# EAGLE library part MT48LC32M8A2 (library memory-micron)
256Mb: x16 SDRAM MT48LC32M8A2 - 8 Meg x 8 x 4 banks Source: http://download.micron.com/pdf/datasheets/dram/sdram/256MSDRAM.pdf
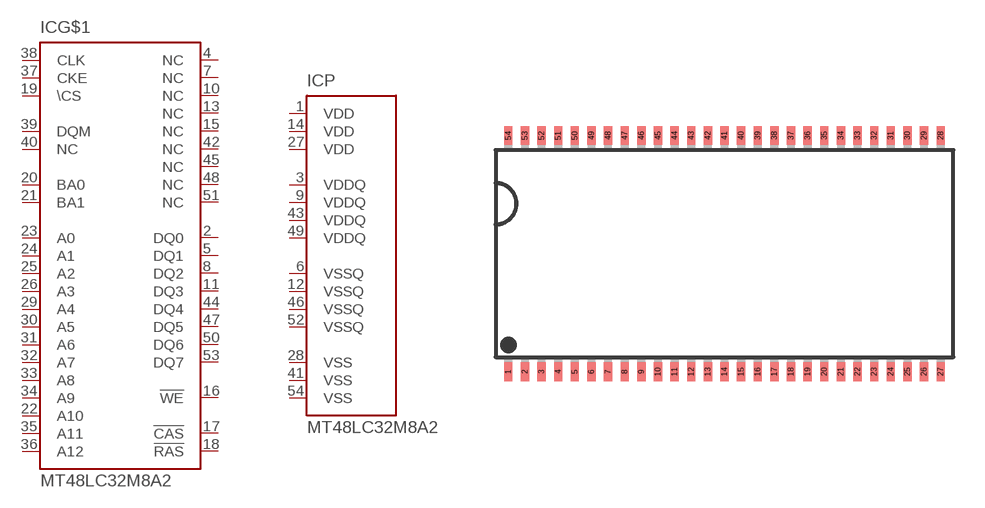
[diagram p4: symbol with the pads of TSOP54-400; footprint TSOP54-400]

Designator prefix IC; gates G$1=MT48LC32M8A2 P=MT48LC64/32/16M-PWR

## MT48LC32M8A2 (MPN: MT48LC32M8A2P-7E:D; OC_FARNELL: 1216283; OC_NEWARK: 97K6122)  [TSOP54-400]
1  P:VDD  pwr
2  G$1:DQ0  hiz
3  P:VDDQ  pwr
4  G$1:NC  nc
5  G$1:DQ1  hiz
6  P:VSSQ  pwr
7  G$1:NC  nc
8  G$1:DQ2  hiz
9  P:VDDQ  pwr
10  G$1:NC  nc
11  G$1:DQ3  hiz
12  P:VSSQ  pwr
13  G$1:NC  nc
14  P:VDD  pwr
15  G$1:NC  nc
16  G$1:!WE  in
17  G$1:!CAS  in
18  G$1:!RAS  in
19  G$1:\CS  in
20  G$1:BA0  in
21  G$1:BA1  in
22  G$1:A10  in
23  G$1:A0  in
24  G$1:A1  in
25  G$1:A2  in
26  G$1:A3  in
27  P:VDD  pwr
28  P:VSS  pwr
29  G$1:A4  in
30  G$1:A5  in
31  G$1:A6  in
32  G$1:A7  in
33  G$1:A8  in
34  G$1:A9  in
35  G$1:A11  in
36  G$1:A12  in
37  G$1:CKE  in
38  G$1:CLK  in
39  G$1:DQM  in
40  G$1:NC  in
41  P:VSS  pwr
42  G$1:NC  nc
43  P:VDDQ  pwr
44  G$1:DQ4  hiz
45  G$1:NC  nc
46  P:VSSQ  pwr
47  G$1:DQ5  hiz
48  G$1:NC  nc
49  P:VDDQ  pwr
50  G$1:DQ6  hiz
51  G$1:NC  nc
52  P:VSSQ  pwr
53  G$1:DQ7  hiz
54  P:VSS  pwr

## Footprint TSOP54-400 (pad centres in mm)
54-Pin Plastic TSOP (400 mil) Source: http://download.micron.com/pdf/datasheets/dram/sdram/256MSDRAM.pdf
smd 0.4 x 0.9: 1 -10.4,-5.68; 2 -9.6,-5.68; 3 -8.8,-5.68; 4 -8,-5.68; 5 -7.2,-5.68; 6 -6.4,-5.68; 7 -5.6,-5.68; 8 -4.8,-5.68; 9 -4,-5.68; 10 -3.2,-5.68; 11 -2.4,-5.68; 12 -1.6,-5.68; 13 -0.8,-5.68; 14 0,-5.68; 15 0.8,-5.68; 16 1.6,-5.68; 17 2.4,-5.68; 18 3.2,-5.68; 19 4,-5.68; 20 4.8,-5.68; 21 5.6,-5.68; 22 6.4,-5.68; 23 7.2,-5.68; 24 8,-5.68; 25 8.8,-5.68; 26 9.6,-5.68; 27 10.4,-5.68; 28 10.4,5.68; 29 9.6,5.68; 30 8.8,5.68; 31 8,5.68; 32 7.2,5.68; 33 6.4,5.68; 34 5.6,5.68; 35 4.8,5.68; 36 4,5.68; 37 3.2,5.68; 38 2.4,5.68; 39 1.6,5.68; 40 0.8,5.68; 41 0,5.68; 42 -0.8,5.68; 43 -1.6,5.68; 44 -2.4,5.68; 45 -3.2,5.68; 46 -4,5.68; 47 -4.8,5.68; 48 -5.6,5.68; 49 -6.4,5.68; 50 -7.2,5.68; 51 -8,5.68; 52 -8.8,5.68; 53 -9.6,5.68; 54 -10.4,5.68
